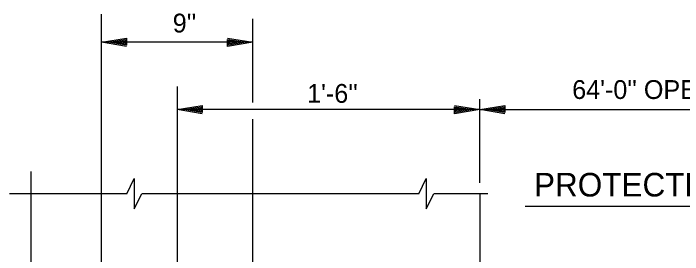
# Model space of a CAD drawing. Extents: x 18232 to 22378, y 12454 to 22381.
# Drawn here: x 22370.537 to 22371.366, y 22373.496 to 22373.795 of the extents above; entities that cross this region are included whole.
import ezdxf

# ---------------------------------------------------------------- set-up
doc = ezdxf.new("R2010")
doc.units = 0
for name, color, linetype in [('Level 1', 7, 'Continuous'), ('Level 2', 7, 'Continuous'), ('Level 3', 7, 'Continuous'), ('Level 50', 7, 'Continuous')]:
    doc.layers.add(name, color=color, linetype=linetype)

msp = doc.modelspace()

# ---------------------------------------------------------------- linework, layer by layer
at = {"layer": 'Level 1'}
for points in [[(22370.67707, 22373.57154), (22370.68639, 22373.59029), (22370.68639, 22373.55283), (22370.69576, 22373.57154)], [(22371.03889, 22373.57154), (22371.0482, 22373.59029), (22371.0482, 22373.55283), (22371.05757, 22373.57154)]]:
    msp.add_lwpolyline(points, dxfattribs=at)
at = {"layer": 'Level 2'}
for p, q in [((22370.8332, 22373.75904), (22370.6457, 22373.75904)), ((22371.11446, 22373.67571), (22370.73945, 22373.67571)), ((22370.55851, 22373.46976), (22370.55851, 22373.59922)), ((22370.67707, 22373.57154), (22370.53161, 22373.57154)), ((22371.03889, 22373.57154), (22370.69576, 22373.57154)), ((22371.12459, 22373.57154), (22371.05757, 22373.57154))]:
    msp.add_line(p, q, dxfattribs=at)
at = {"layer": 'Level 3'}
for p, q in [((22370.6457, 22373.37721), (22370.6457, 22373.79401)), ((22370.8332, 22373.68447), (22370.8332, 22373.78805)), ((22370.6457, 22373.75904), (22370.6457, 22373.75904)), ((22370.65436, 22373.75904), (22370.65436, 22373.75904)), ((22370.82453, 22373.75904), (22370.82453, 22373.75904)), ((22370.8332, 22373.75904), (22370.8332, 22373.75904)), ((22370.73946, 22373.70455), (22370.73946, 22372.9306)), ((22371.11446, 22373.58508), (22371.11446, 22373.68885)), ((22371.10579, 22373.67571), (22371.10579, 22373.67571)), ((22371.11446, 22373.67571), (22371.50617, 22373.67571)), ((22371.11446, 22373.67571), (22371.11446, 22373.67571)), ((22371.11446, 22373.67571), (22371.11446, 22373.67571)), ((22371.12313, 22373.67571), (22371.12313, 22373.67571)), ((22370.8332, 22373.37995), (22370.8332, 22373.66405)), ((22371.11446, 22373.57154), (22371.11446, 22373.35217)), ((22371.17075, 22373.55626), (22371.55124, 22373.55626))]:
    msp.add_line(p, q, dxfattribs=at)
for points in [[(22370.67686, 22373.75388), (22370.6457, 22373.75904), (22370.67686, 22373.76421), (22370.67686, 22373.75538), (22370.65436, 22373.75904), (22370.67553, 22373.76254), (22370.67553, 22373.75688), (22370.6627, 22373.75904), (22370.6742, 22373.76088), (22370.6742, 22373.75854), (22370.67136, 22373.75904)], [(22370.80203, 22373.76421), (22370.8332, 22373.75904), (22370.80203, 22373.75388), (22370.80203, 22373.76271), (22370.82453, 22373.75904), (22370.80336, 22373.75554), (22370.80336, 22373.76121), (22370.8162, 22373.75904), (22370.8047, 22373.75721), (22370.8047, 22373.75954), (22370.80753, 22373.75904)], [(22371.08329, 22373.68088), (22371.11446, 22373.67571), (22371.08329, 22373.67054), (22371.08329, 22373.67938), (22371.10579, 22373.67571), (22371.08463, 22373.67221), (22371.08463, 22373.67788), (22371.09746, 22373.67571), (22371.08596, 22373.67388), (22371.08596, 22373.67621), (22371.08879, 22373.67571)], [(22371.14563, 22373.67054), (22371.11446, 22373.67571), (22371.14563, 22373.68088), (22371.14563, 22373.67204), (22371.12313, 22373.67571), (22371.14429, 22373.67921), (22371.14429, 22373.67354), (22371.13146, 22373.67571), (22371.14296, 22373.67754), (22371.14296, 22373.67521), (22371.14013, 22373.67571)]]:
    msp.add_lwpolyline(points, dxfattribs=at)
at = {"layer": 'Level 50'}
for p, q in [((22370.73945, 22373.67571), (22370.73945, 22373.67571)), ((22370.74811, 22373.67571), (22370.74811, 22373.67571))]:
    msp.add_line(p, q, dxfattribs=at)
msp.add_lwpolyline([(22370.77061, 22373.67054), (22370.73945, 22373.67571), (22370.77061, 22373.68088), (22370.77061, 22373.67204), (22370.74811, 22373.67571), (22370.76928, 22373.67921), (22370.76928, 22373.67354), (22370.75645, 22373.67571), (22370.76795, 22373.67754), (22370.76795, 22373.67521), (22370.76511, 22373.67571)], dxfattribs=at)

# ---------------------------------------------------------------- texts
at = {"layer": 'Level 3'}
for s, height, p in [("9''", 0.023292, (22370.73407, 22373.77121)), ("64'-0'' OPENING", 0.0232917, (22371.22914, 22373.68893)), ("1'-6''", 0.023292, (22370.90063, 22373.68416)), ('PROTECTED SIDE', 0.0291979, (22371.18177, 22373.56821))]:
    msp.add_text(s, height=height, dxfattribs=at).set_placement(p)

doc.saveas('drawing.dxf')
